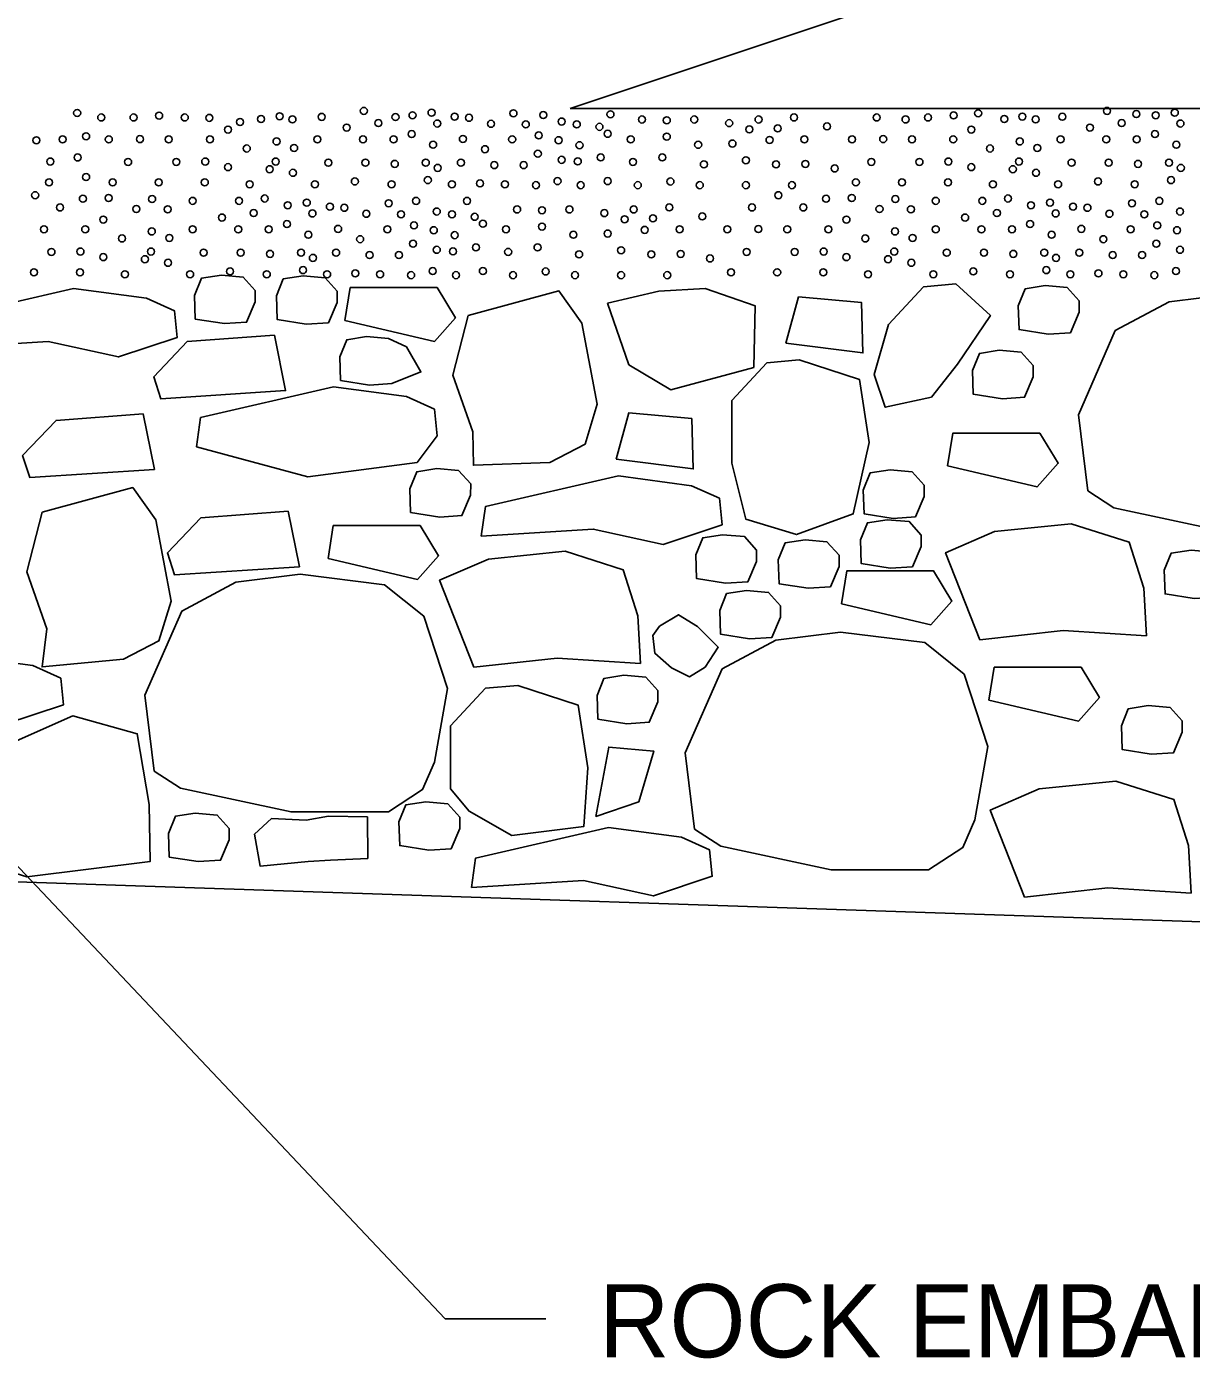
# Model space of a CAD drawing. Extents: x 2189223 to 2190097, y 563994 to 564498.
# Drawn here: x 2189459.3 to 2189501.45, y 564100.43 to 564148.61 of the extents above; entities that cross this region are included whole.
import ezdxf

# ---------------------------------------------------------------- set-up
doc = ezdxf.new("R2010")
doc.units = 0
for name, color, linetype in [('Default', 7, 'Continuous'), ('Exist XS Ground Line', 7, 'Continuous'), ('Prop XS Earthwork Rock Weathered Degradable', 7, 'Continuous')]:
    doc.layers.add(name, color=color, linetype=linetype)

msp = doc.modelspace()

# ---------------------------------------------------------------- linework, layer by layer
at = {"layer": 'Default'}
for p, q in [((2189454.83, 564122.61), (2189474.442, 564101.853)), ((2189474.442, 564101.853), (2189478.084, 564101.853))]:
    msp.add_line(p, q, dxfattribs=at)
msp.add_lwpolyline([(2189578.615, 564178.866), (2189478.962, 564145.652)], dxfattribs=at)
for points in [[(2189467.574, 564139.065), (2189467.137, 564139.549), (2189466.344, 564139.62), (2189465.623, 564139.506), (2189465.372, 564138.888), (2189465.402, 564138.03), (2189466.453, 564137.865), (2189467.258, 564137.917), (2189467.573, 564138.655)], [(2189470.537, 564139.043), (2189470.1, 564139.527), (2189469.307, 564139.598), (2189468.586, 564139.485), (2189468.335, 564138.866), (2189468.365, 564138.008), (2189469.416, 564137.843), (2189470.221, 564137.895), (2189470.536, 564138.633)], [(2189456.028, 564136.962), (2189460.083, 564137.215), (2189462.618, 564136.659), (2189464.747, 564137.367), (2189464.645, 564138.328), (2189463.631, 564138.783), (2189460.996, 564139.137), (2189456.18, 564138.024)], [(2189470.815, 564137.98), (2189474.054, 564137.219), (2189474.816, 564138.075), (2189474.149, 564139.168), (2189471.006, 564139.168)], [(2189475.281, 564138.163), (2189474.725, 564136), (2189475.448, 564133.948), (2189475.466, 564132.739), (2189478.227, 564132.838), (2189479.505, 564133.504), (2189479.95, 564134.946), (2189479.394, 564137.885), (2189478.56, 564139.05)], [(2189480.323, 564138.609), (2189481.085, 564136.376), (2189482.609, 564135.473), (2189485.609, 564136.281), (2189485.657, 564138.514), (2189483.847, 564139.132), (2189482.181, 564139.037)], [(2189491.752, 564139.2), (2189490.485, 564137.835), (2189489.971, 564136.028), (2189490.367, 564134.84), (2189492.042, 564135.206), (2189492.987, 564136.394), (2189494.174, 564138.162), (2189494.174, 564138.162), (2189492.918, 564139.302)], [(2189497.386, 564138.684), (2189496.95, 564139.169), (2189496.156, 564139.24), (2189495.435, 564139.126), (2189495.184, 564138.508), (2189495.214, 564137.65), (2189496.266, 564137.485), (2189497.07, 564137.537), (2189497.385, 564138.275)], [(2189497.694, 564131.813), (2189498.646, 564131.196), (2189502.646, 564130.34), (2189506.17, 564130.34), (2189507.409, 564131.148), (2189507.837, 564132.146), (2189508.314, 564134.807), (2189507.457, 564137.42), (2189506.028, 564138.56), (2189502.98, 564138.941), (2189500.646, 564138.655), (2189498.694, 564137.61), (2189497.36, 564134.569)], [(2189486.775, 564137.16), (2189489.563, 564136.806), (2189489.512, 564138.626), (2189487.231, 564138.829)], [(2189468.264, 564137.448), (2189465.106, 564137.212), (2189463.896, 564135.942), (2189464.153, 564135.149), (2189468.67, 564135.439)], [(2189473.039, 564137.029), (2189472.394, 564137.326), (2189471.601, 564137.397), (2189470.88, 564137.283), (2189470.629, 564136.664), (2189470.659, 564135.807), (2189471.71, 564135.641), (2189472.515, 564135.694), (2189473.567, 564136.117)], [(2189486.089, 564136.451), (2189484.821, 564135.086), (2189484.821, 564132.81), (2189485.328, 564130.787), (2189487.153, 564130.231), (2189489.212, 564130.977), (2189489.789, 564133.568), (2189489.434, 564135.844), (2189487.255, 564136.552)], [(2189495.726, 564136.346), (2189495.29, 564136.83), (2189494.496, 564136.901), (2189493.775, 564136.788), (2189493.524, 564136.169), (2189493.554, 564135.311), (2189494.606, 564135.146), (2189495.41, 564135.198), (2189495.725, 564135.936)], [(2189465.439, 564133.402), (2189469.478, 564132.32), (2189473.429, 564132.837), (2189474.157, 564133.807), (2189474.055, 564134.768), (2189473.042, 564135.223), (2189470.406, 564135.577), (2189465.591, 564134.464)], [(2189463.519, 564134.6), (2189460.362, 564134.364), (2189459.152, 564133.094), (2189459.408, 564132.3), (2189463.925, 564132.591)], [(2189480.631, 564132.962), (2189483.419, 564132.608), (2189483.368, 564134.428), (2189481.087, 564134.631)], [(2189492.626, 564132.716), (2189495.865, 564131.956), (2189496.627, 564132.811), (2189495.96, 564133.904), (2189492.817, 564133.904)], [(2189475.367, 564132.066), (2189474.93, 564132.55), (2189474.137, 564132.621), (2189473.416, 564132.508), (2189473.165, 564131.889), (2189473.195, 564131.031), (2189474.246, 564130.866), (2189475.051, 564130.918), (2189475.366, 564131.656)], [(2189475.748, 564130.18), (2189479.803, 564130.433), (2189482.338, 564129.877), (2189484.467, 564130.585), (2189484.365, 564131.546), (2189483.352, 564132.001), (2189480.716, 564132.355), (2189475.9, 564131.242)], [(2189491.774, 564132.019), (2189491.338, 564132.503), (2189490.544, 564132.574), (2189489.823, 564132.461), (2189489.572, 564131.842), (2189489.602, 564130.984), (2189490.654, 564130.819), (2189491.458, 564130.871), (2189491.773, 564131.609)], [(2189459.86, 564131.042), (2189459.305, 564128.879), (2189460.027, 564126.827), (2189459.86, 564125.441), (2189462.806, 564125.718), (2189464.085, 564126.384), (2189464.53, 564127.826), (2189463.974, 564130.765), (2189463.14, 564131.93)], [(2189468.761, 564131.073), (2189465.603, 564130.837), (2189464.393, 564129.568), (2189464.65, 564128.774), (2189469.167, 564129.065)], [(2189491.671, 564130.215), (2189491.235, 564130.7), (2189490.442, 564130.771), (2189489.721, 564130.657), (2189489.47, 564130.038), (2189489.5, 564129.181), (2189490.551, 564129.015), (2189491.355, 564129.068), (2189491.67, 564129.806)], [(2189470.204, 564129.369), (2189473.442, 564128.608), (2189474.205, 564129.464), (2189473.538, 564130.557), (2189470.395, 564130.557)], [(2189493.797, 564126.427), (2189496.809, 564126.761), (2189499.821, 564126.57), (2189499.725, 564128.287), (2189499.199, 564129.957), (2189497.096, 564130.625), (2189494.323, 564130.339), (2189492.553, 564129.575)], [(2189485.713, 564129.672), (2189485.276, 564130.157), (2189484.483, 564130.228), (2189483.762, 564130.114), (2189483.511, 564129.495), (2189483.541, 564128.638), (2189484.592, 564128.472), (2189485.397, 564128.525), (2189485.712, 564129.263)], [(2189488.698, 564129.489), (2189488.261, 564129.974), (2189487.468, 564130.045), (2189486.747, 564129.931), (2189486.496, 564129.313), (2189486.526, 564128.455), (2189487.577, 564128.289), (2189488.382, 564128.342), (2189488.697, 564129.08)], [(2189475.485, 564125.43), (2189478.497, 564125.764), (2189481.51, 564125.573), (2189481.414, 564127.29), (2189480.888, 564128.96), (2189478.784, 564129.628), (2189476.011, 564129.342), (2189474.242, 564128.578)], [(2189502.665, 564129.116), (2189502.229, 564129.601), (2189501.436, 564129.672), (2189500.715, 564129.558), (2189500.464, 564128.94), (2189500.493, 564128.082), (2189501.545, 564127.917), (2189502.349, 564127.969), (2189502.664, 564128.707)], [(2189463.914, 564121.669), (2189464.866, 564121.051), (2189468.867, 564120.196), (2189472.391, 564120.196), (2189473.629, 564121.004), (2189474.057, 564122.001), (2189474.534, 564124.662), (2189473.677, 564127.276), (2189472.248, 564128.416), (2189469.2, 564128.796), (2189466.866, 564128.511), (2189464.914, 564127.466), (2189463.58, 564124.425)], [(2189488.783, 564127.731), (2189492.021, 564126.97), (2189492.783, 564127.826), (2189492.116, 564128.919), (2189488.973, 564128.919)], [(2189486.581, 564127.657), (2189486.145, 564128.142), (2189485.352, 564128.213), (2189484.63, 564128.099), (2189484.38, 564127.48), (2189484.409, 564126.623), (2189485.461, 564126.457), (2189486.265, 564126.51), (2189486.58, 564127.248)], [(2189481.96, 564126.584), (2189482.031, 564125.936), (2189482.633, 564125.414), (2189483.285, 564125.085), (2189483.85, 564125.44), (2189484.327, 564126.153), (2189483.571, 564126.902), (2189482.888, 564127.33), (2189482.201, 564126.915)], [(2189483.462, 564119.574), (2189484.414, 564118.956), (2189488.415, 564118.101), (2189491.939, 564118.101), (2189493.177, 564118.909), (2189493.605, 564119.906), (2189494.082, 564122.567), (2189493.225, 564125.181), (2189491.796, 564126.321), (2189488.748, 564126.701), (2189486.414, 564126.416), (2189484.462, 564125.371), (2189483.128, 564122.33)], [(2189451.916, 564123.671), (2189455.971, 564123.924), (2189458.505, 564123.367), (2189460.634, 564124.076), (2189460.533, 564125.036), (2189459.519, 564125.491), (2189456.883, 564125.846), (2189452.068, 564124.733)], [(2189494.121, 564124.241), (2189497.36, 564123.481), (2189498.122, 564124.336), (2189497.455, 564125.429), (2189494.312, 564125.429)], [(2189482.142, 564124.587), (2189481.705, 564125.072), (2189480.912, 564125.143), (2189480.191, 564125.029), (2189479.94, 564124.411), (2189479.97, 564123.553), (2189481.021, 564123.388), (2189481.826, 564123.44), (2189482.141, 564124.178)], [(2189475.906, 564124.671), (2189474.638, 564123.306), (2189474.638, 564121.03), (2189475.311, 564120.224), (2189476.858, 564119.347), (2189479.464, 564119.672), (2189479.606, 564121.789), (2189479.251, 564124.065), (2189477.072, 564124.773)], [(2189501.116, 564123.487), (2189500.679, 564123.972), (2189499.886, 564124.043), (2189499.165, 564123.929), (2189498.914, 564123.31), (2189498.944, 564122.453), (2189499.995, 564122.287), (2189500.8, 564122.34), (2189501.115, 564123.077)], [(2189458.263, 564122.484), (2189457.308, 564122.303), (2189456.971, 564120.433), (2189457.478, 564118.41), (2189459.302, 564117.854), (2189463.763, 564118.403), (2189463.731, 564120.468), (2189463.299, 564123.027), (2189460.975, 564123.673)], [(2189479.891, 564120.037), (2189481.449, 564120.562), (2189481.99, 564122.399), (2189480.363, 564122.543)], [(2189495.414, 564117.117), (2189498.426, 564117.451), (2189501.438, 564117.26), (2189501.342, 564118.977), (2189500.816, 564120.647), (2189498.713, 564121.315), (2189495.94, 564121.029), (2189494.17, 564120.265)], [(2189466.631, 564119.597), (2189466.194, 564120.082), (2189465.401, 564120.153), (2189464.68, 564120.039), (2189464.429, 564119.42), (2189464.459, 564118.563), (2189465.51, 564118.397), (2189466.315, 564118.45), (2189466.629, 564119.188)], [(2189474.971, 564120.011), (2189474.535, 564120.495), (2189473.741, 564120.566), (2189473.02, 564120.452), (2189472.769, 564119.834), (2189472.799, 564118.976), (2189473.85, 564118.811), (2189474.655, 564118.863), (2189474.97, 564119.601)], [(2189471.629, 564120.019), (2189470.225, 564120.048), (2189469.417, 564119.899), (2189468.16, 564119.957), (2189467.548, 564119.391), (2189467.749, 564118.233), (2189469.487, 564118.397), (2189470.291, 564118.45), (2189471.644, 564118.514)], [(2189475.391, 564117.464), (2189479.446, 564117.717), (2189481.98, 564117.16), (2189484.109, 564117.869), (2189484.008, 564118.829), (2189482.994, 564119.284), (2189480.358, 564119.638), (2189475.543, 564118.526)]]:
    msp.add_lwpolyline(points, close=True, dxfattribs=at)
for centre in [(2189471.5, 564145.563), (2189498.395, 564145.563), (2189461.127, 564145.486), (2189461.997, 564145.323), (2189463.166, 564145.323), (2189464.093, 564145.391), (2189465.022, 564145.323), (2189465.906, 564145.31), (2189467.021, 564145.16), (2189467.781, 564145.268), (2189468.453, 564145.368), (2189468.918, 564145.255), (2189469.977, 564145.346), (2189472.028, 564145.122), (2189472.646, 564145.339), (2189473.262, 564145.404), (2189473.951, 564145.497), (2189474.156, 564145.105), (2189474.786, 564145.353), (2189475.307, 564145.312), (2189476.103, 564145.094), (2189476.915, 564145.474), (2189477.362, 564145.074), (2189477.993, 564145.412), (2189478.656, 564145.177), (2189479.207, 564145.074), (2189480.426, 564145.438), (2189481.563, 564145.25), (2189482.463, 564145.221), (2189483.456, 564145.25), (2189484.721, 564145.118), (2189485.783, 564145.25), (2189487.067, 564145.324), (2189490.061, 564145.323), (2189491.103, 564145.252), (2189491.917, 564145.323), (2189492.843, 564145.398), (2189493.731, 564145.476), (2189494.676, 564145.268), (2189495.33, 564145.356), (2189495.812, 564145.255), (2189496.776, 564145.35), (2189498.923, 564145.122), (2189499.455, 564145.447), (2189500.156, 564145.404), (2189500.846, 564145.497), (2189501.051, 564145.105), (2189461.451, 564144.644), (2189466.586, 564144.884), (2189470.88, 564144.958), (2189473.232, 564144.722), (2189477.83, 564144.675), (2189480.028, 564144.985), (2189480.323, 564144.734), (2189482.463, 564144.63), (2189485.451, 564144.894), (2189486.478, 564144.929), (2189488.262, 564145), (2189493.481, 564144.884), (2189497.775, 564144.958), (2189500.127, 564144.722), (2189459.651, 564144.497), (2189460.6, 564144.532), (2189462.272, 564144.532), (2189463.399, 564144.541), (2189464.441, 564144.532), (2189465.932, 564144.532), (2189467.265, 564144.201), (2189468.342, 564144.456), (2189468.977, 564144.22), (2189469.819, 564144.532), (2189471.47, 564144.532), (2189472.575, 564144.532), (2189474.008, 564144.338), (2189475.085, 564144.548), (2189475.882, 564144.175), (2189476.868, 564144.532), (2189478.546, 564144.5), (2189479.305, 564144.32), (2189481.161, 564144.532), (2189483.599, 564144.335), (2189484.839, 564144.38), (2189486.181, 564144.512), (2189487.442, 564144.532), (2189489.167, 564144.532), (2189490.294, 564144.541), (2189491.336, 564144.532), (2189492.827, 564144.532), (2189494.16, 564144.201), (2189495.237, 564144.456), (2189495.871, 564144.22), (2189496.713, 564144.532), (2189498.365, 564144.532), (2189499.47, 564144.532), (2189500.903, 564144.338), (2189460.153, 564143.729), (2189461.142, 564143.877), (2189462.971, 564143.714), (2189464.712, 564143.714), (2189465.76, 564143.729), (2189468.313, 564143.729), (2189470.216, 564143.688), (2189471.559, 564143.688), (2189472.621, 564143.644), (2189473.743, 564143.688), (2189475.012, 564143.688), (2189476.221, 564143.6), (2189477.284, 564143.6), (2189477.797, 564144.012), (2189478.656, 564143.791), (2189479.242, 564143.734), (2189480.073, 564143.878), (2189481.238, 564143.715), (2189482.301, 564143.878), (2189483.806, 564143.627), (2189485.325, 564143.774), (2189486.417, 564143.627), (2189487.48, 564143.641), (2189489.866, 564143.714), (2189491.607, 564143.714), (2189492.655, 564143.729), (2189495.207, 564143.729), (2189497.111, 564143.688), (2189498.454, 564143.688), (2189499.516, 564143.644), (2189500.637, 564143.688), (2189461.451, 564143.168), (2189466.586, 564143.526), (2189468.091, 564143.452), (2189468.932, 564143.321), (2189474.171, 564143.499), (2189488.542, 564143.479), (2189493.481, 564143.526), (2189494.986, 564143.452), (2189495.827, 564143.321), (2189501.065, 564143.499), (2189460.109, 564142.976), (2189462.411, 564142.976), (2189464.078, 564142.976), (2189465.745, 564142.976), (2189467.368, 564142.906), (2189469.729, 564142.906), (2189471.175, 564143.009), (2189472.503, 564142.906), (2189473.816, 564143.056), (2189474.687, 564142.906), (2189475.705, 564142.939), (2189476.605, 564142.906), (2189477.727, 564142.874), (2189478.509, 564143.021), (2189479.35, 564142.874), (2189480.323, 564143.021), (2189481.415, 564142.874), (2189482.596, 564143.007), (2189483.658, 564142.874), (2189485.325, 564142.874), (2189486.993, 564142.874), (2189489.305, 564142.976), (2189490.973, 564142.976), (2189492.64, 564142.976), (2189494.263, 564142.906), (2189496.624, 564142.906), (2189498.07, 564143.009), (2189499.398, 564142.906), (2189500.711, 564143.056), (2189459.607, 564142.51), (2189461.334, 564142.383), (2189462.263, 564142.41), (2189463.839, 564142.371), (2189465.303, 564142.307), (2189466.985, 564142.307), (2189467.914, 564142.392), (2189468.747, 564142.148), (2189469.436, 564142.242), (2189472.4, 564142.219), (2189473.392, 564142.305), (2189475.233, 564142.305), (2189486.502, 564142.51), (2189488.228, 564142.383), (2189489.158, 564142.41), (2189490.734, 564142.371), (2189492.198, 564142.307), (2189493.88, 564142.307), (2189494.809, 564142.392), (2189495.641, 564142.148), (2189496.331, 564142.242), (2189499.295, 564142.219), (2189500.287, 564142.305), (2189460.507, 564142.068), (2189463.267, 564142.012), (2189464.403, 564142), (2189466.365, 564141.702), (2189467.513, 564141.866), (2189469.641, 564141.85), (2189470.271, 564142.097), (2189470.792, 564142.056), (2189471.588, 564141.839), (2189472.847, 564141.819), (2189474.141, 564141.921), (2189474.692, 564141.819), (2189475.513, 564141.729), (2189477.048, 564141.995), (2189477.948, 564141.965), (2189478.941, 564141.995), (2189480.206, 564141.862), (2189481.268, 564141.995), (2189481.963, 564141.674), (2189482.552, 564142.069), (2189483.747, 564141.744), (2189485.546, 564142.068), (2189487.402, 564142.068), (2189490.161, 564142.012), (2189491.297, 564142), (2189493.26, 564141.702), (2189494.408, 564141.866), (2189496.536, 564141.85), (2189497.166, 564142.097), (2189497.687, 564142.056), (2189498.483, 564141.839), (2189499.742, 564141.819), (2189501.036, 564141.921), (2189459.926, 564141.277), (2189461.418, 564141.277), (2189462.071, 564141.628), (2189463.827, 564141.2), (2189465.304, 564141.277), (2189466.955, 564141.276), (2189468.06, 564141.277), (2189468.717, 564141.466), (2189470.57, 564141.292), (2189472.353, 564141.277), (2189473.315, 564141.419), (2189474.031, 564141.244), (2189475.808, 564141.478), (2189476.646, 564141.277), (2189477.948, 564141.375), (2189480.936, 564141.639), (2189481.666, 564141.257), (2189482.927, 564141.277), (2189484.652, 564141.277), (2189485.779, 564141.285), (2189486.821, 564141.277), (2189488.312, 564141.277), (2189488.966, 564141.628), (2189490.722, 564141.2), (2189492.198, 564141.277), (2189493.85, 564141.276), (2189494.955, 564141.277), (2189495.612, 564141.466), (2189497.465, 564141.292), (2189499.248, 564141.277), (2189500.21, 564141.419), (2189500.926, 564141.244), (2189462.75, 564140.946), (2189464.462, 564140.964), (2189469.493, 564141.082), (2189471.367, 564140.92), (2189473.282, 564140.757), (2189474.79, 564141.065), (2189479.084, 564141.08), (2189480.324, 564141.124), (2189489.645, 564140.946), (2189491.357, 564140.964), (2189496.388, 564141.082), (2189498.262, 564140.92), (2189500.177, 564140.757), (2189460.197, 564140.459), (2189461.245, 564140.473), (2189462.071, 564140.27), (2189463.798, 564140.473), (2189465.701, 564140.432), (2189467.044, 564140.432), (2189468.106, 564140.388), (2189469.228, 564140.432), (2189469.656, 564140.243), (2189470.497, 564140.432), (2189471.707, 564140.344), (2189472.769, 564140.344), (2189474.141, 564140.535), (2189474.727, 564140.478), (2189475.558, 564140.622), (2189476.723, 564140.46), (2189477.786, 564140.622), (2189479.291, 564140.371), (2189480.811, 564140.519), (2189481.902, 564140.371), (2189482.965, 564140.386), (2189484.027, 564140.223), (2189485.351, 564140.459), (2189487.092, 564140.459), (2189488.14, 564140.473), (2189488.966, 564140.27), (2189490.693, 564140.473), (2189492.596, 564140.432), (2189493.939, 564140.432), (2189495.001, 564140.388), (2189496.122, 564140.432), (2189496.55, 564140.243), (2189497.391, 564140.432), (2189498.601, 564140.344), (2189499.664, 564140.344), (2189501.036, 564140.535), (2189463.576, 564140.196), (2189464.417, 564140.066), (2189466.66, 564139.753), (2189469.301, 564139.8), (2189473.994, 564139.766), (2189475.808, 564139.766), (2189478.081, 564139.751), (2189490.471, 564140.196), (2189491.312, 564140.066), (2189493.555, 564139.753), (2189496.196, 564139.8), (2189500.888, 564139.766), (2189459.563, 564139.72), (2189461.23, 564139.72), (2189462.853, 564139.65), (2189465.214, 564139.65), (2189467.988, 564139.65), (2189470.172, 564139.65), (2189471.19, 564139.683), (2189472.09, 564139.65), (2189473.212, 564139.618), (2189474.835, 564139.618), (2189476.9, 564139.618), (2189479.143, 564139.618), (2189480.811, 564139.618), (2189482.478, 564139.618), (2189484.79, 564139.72), (2189486.458, 564139.72), (2189488.125, 564139.72), (2189489.748, 564139.65), (2189492.109, 564139.65), (2189494.883, 564139.65), (2189497.067, 564139.65), (2189498.085, 564139.683), (2189498.985, 564139.65), (2189500.106, 564139.618)]:
    msp.add_circle(centre, 0.127, dxfattribs=at)
at = {"layer": 'Exist XS Ground Line'}
msp.add_line((2189369.91, 564120.674), (2189520.23, 564115.595), dxfattribs=at)
at = {"layer": 'Prop XS Earthwork Rock Weathered Degradable'}
msp.add_line((2189545.494, 564145.652), (2189478.962, 564145.652), dxfattribs=at)

# ---------------------------------------------------------------- texts
at = {"layer": 'Default'}
msp.add_text('ROCK EMBANKMENTS ', height=2.64588, dxfattribs=at).set_placement((2189480.006, 564100.463))

doc.saveas('drawing.dxf')
